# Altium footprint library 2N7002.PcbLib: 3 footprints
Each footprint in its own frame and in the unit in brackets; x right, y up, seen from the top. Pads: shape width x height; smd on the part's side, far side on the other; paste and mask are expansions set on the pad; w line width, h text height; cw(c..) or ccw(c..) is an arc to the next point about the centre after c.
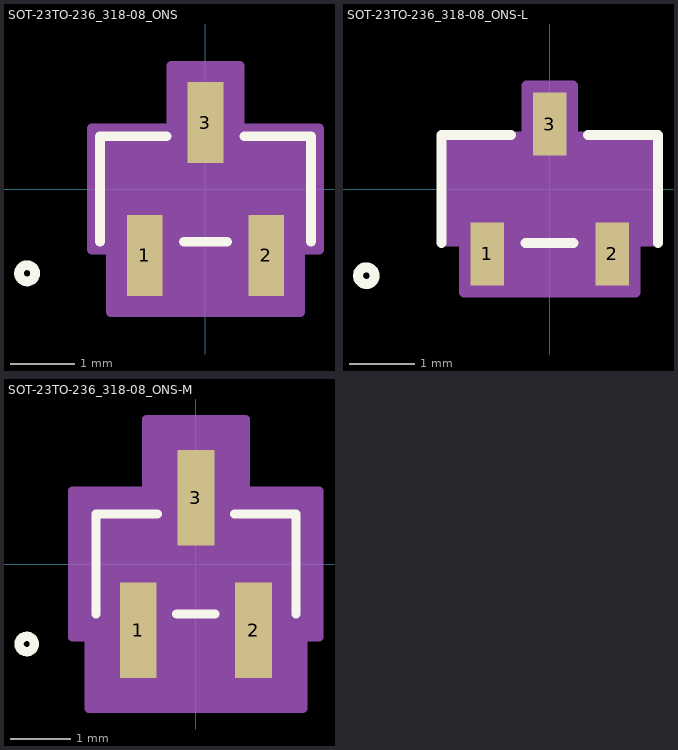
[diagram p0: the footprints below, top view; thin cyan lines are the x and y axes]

## SOT-23TO-236_318-08_ONS [mil]
pads (3):
  rect 22x50 smd paste+0 mask+0: 1(-37.5,-41) 2(37.5,-41) 3(0,41)
Top Overlay:
  circle w6: c-110,-52 r5
  lines w6: -65,-32.5 -65,32.5 -24.1,32.5 ; -13.4,-32.5 13.4,-32.5 ; 24.1,32.5 65,32.5 65,-32.5
  text ".Designator" at -137.5,-25 h50
Mechanical 13:
  circle w1: c-50,-17.5 r5
  lines w1: -60,-27.5 60,-27.5 60,27.5 -60,27.5 -60,-27.5 ; -47.5,-52 -47.5,-27.5 -27.5,-27.5 -27.5,-52 -47.5,-52 ; -10,27.5 10,27.5 10,52 -10,52 -10,27.5 ; 27.5,-52 27.5,-27.5 47.5,-27.5 47.5,-52 27.5,-52
  text ".Designator" at -137.5,-25 h50
Mechanical 15:
  region: -70,-37.5 -70,37.5 -21,37.5 -21,76 21,76 21,37.5 70,37.5 70,-37.5 58.5,-37.5 58.5,-76 -58.5,-76 -58.5,-37.5
  region: 60,-27.5 -60,-27.5 -60,27.5 60,27.5
  lines w6: -70,-37.5 -70,37.5 -21,37.5 -21,76 21,76 21,37.5 70,37.5 70,-37.5 58.5,-37.5 58.5,-76 -58.5,-76 -58.5,-37.5 -70,-37.5
3D body "SOT-23TO-236_318-08_ONS.step": height 44.09, standoff 0, extent -60,-52.01 60,52.01

## SOT-23TO-236_318-08_ONS-L [mil]
pads (3):
  rect 20x38 smd paste+0 mask+0: 1(-37.5,-39) 2(37.5,-39) 3(0,39)
Top Overlay:
  circle w6: c-110,-52 r5
  lines w6: -65,-32.5 -65,32.5 -23.1,32.5 ; -14.4,-32.5 14.4,-32.5 ; 23.1,32.5 65,32.5 65,-32.5
  text ".Designator" at -137.5,-25 h50
Mechanical 13:
  circle w1: c-50,-17.5 r5
  lines w1: -60,-27.5 60,-27.5 60,27.5 -60,27.5 -60,-27.5 ; -47.5,-52 -47.5,-27.5 -27.5,-27.5 -27.5,-52 -47.5,-52 ; -10,27.5 10,27.5 10,52 -10,52 -10,27.5 ; 27.5,-52 27.5,-27.5 47.5,-27.5 47.5,-52 27.5,-52
  text ".Designator" at -137.5,-25 h50
Mechanical 15:
  region: -64,-31.5 -64,31.5 -14,31.5 -14,62 14,62 14,31.5 64,31.5 64,-31.5 51.5,-31.5 51.5,-62 -51.5,-62 -51.5,-31.5
  region: 60,-27.5 -60,-27.5 -60,27.5 60,27.5
  lines w6: -64,-31.5 -64,31.5 -14,31.5 -14,62 14,62 14,31.5 64,31.5 64,-31.5 51.5,-31.5 51.5,-62 -51.5,-62 -51.5,-31.5 -64,-31.5
3D body "SOT-23TO-236_318-08_ONS.step": height 44.09, standoff 0, extent -60,-52.01 60,52.01

## SOT-23TO-236_318-08_ONS-M [mil]
pads (3):
  rect 24x62 smd paste+0 mask+0: 1(-37.5,-43) 2(37.5,-43) 3(0,43)
Top Overlay:
  circle w6: c-110,-52 r5
  lines w6: -65,-32.5 -65,32.5 -25.1,32.5 ; -12.4,-32.5 12.4,-32.5 ; 25.1,32.5 65,32.5 65,-32.5
  text ".Designator" at -137.5,-25 h50
Mechanical 13:
  circle w1: c-50,-17.5 r5
  lines w1: -60,-27.5 60,-27.5 60,27.5 -60,27.5 -60,-27.5 ; -47.5,-52 -47.5,-27.5 -27.5,-27.5 -27.5,-52 -47.5,-52 ; -10,27.5 10,27.5 10,52 -10,52 -10,27.5 ; 27.5,-52 27.5,-27.5 47.5,-27.5 47.5,-52 27.5,-52
  text ".Designator" at -137.5,-25 h50
Mechanical 15:
  region: -80,-47.5 -80,47.5 -32,47.5 -32,94 32,94 32,47.5 80,47.5 80,-47.5 69.5,-47.5 69.5,-94 -69.5,-94 -69.5,-47.5
  region: 60,-27.5 -60,-27.5 -60,27.5 60,27.5
  lines w6: -80,-47.5 -80,47.5 -32,47.5 -32,94 32,94 32,47.5 80,47.5 80,-47.5 69.5,-47.5 69.5,-94 -69.5,-94 -69.5,-47.5 -80,-47.5
3D body "SOT-23TO-236_318-08_ONS.step": height 44.09, standoff 0, extent -60,-52.01 60,52.01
